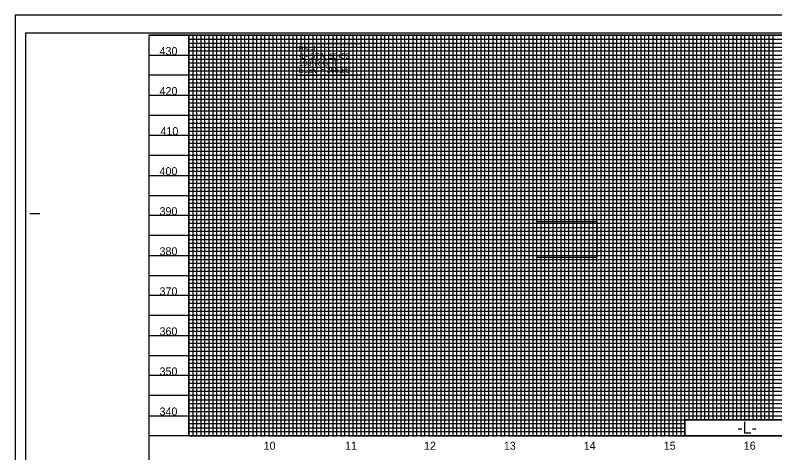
# Model space of a CAD drawing. Extents: x 1629887 to 1632095, y 1174261 to 1175361.
# Drawn here: x 1629887 to 1630837, y 1174814 to 1175361 of the extents above; entities that cross this region are included whole.
import ezdxf

# ---------------------------------------------------------------- set-up
doc = ezdxf.new("R2010")
doc.units = 0
for name, color, linetype in [('Exist Vertical Profile Horizontal Axis Label Major', 7, 'Continuous'), ('Exist Vertical Profile Vertical Axis Label', 7, 'Continuous'), ('Prop DSN Text', 7, 'Continuous'), ('Prop Grid Mask', 7, 'Continuous'), ('Sheet Data Field CELL', 7, 'Continuous'), ('Sheet Layout Profile Border Port 1', 7, 'Continuous'), ('Sheet Plot Border Inside CELL', 7, 'Continuous'), ('Sheet Plot Border Outside CELL', 7, 'Continuous'), ('Sheet Profile CELL', 7, 'Continuous'), ('Sheet Profile Grid Major CELL', 7, 'Continuous'), ('Sheet Profile Grid Middle CELL', 7, 'Continuous'), ('Sheet Profile Grid Minor CELL', 7, 'Continuous')]:
    doc.layers.add(name, color=color, linetype=linetype)

msp = doc.modelspace()

# ---------------------------------------------------------------- linework, layer by layer
at = {"layer": 'Prop Grid Mask'}
for points in [[(1630239.31, 1175325.5), (1630319.31, 1175325.5), (1630319.31, 1175285.5), (1630239.31, 1175285.5)], [(1630539.31, 1175103.2), (1630614.31, 1175103.2), (1630614.31, 1175058.2), (1630539.31, 1175058.2)]]:
    msp.add_lwpolyline(points, close=True, dxfattribs=at)
at = {"layer": 'Sheet Data Field CELL'}
msp.add_lwpolyline([(1630724.31, 1174835.79), (1630884.31, 1174835.79), (1630884.31, 1174855.79), (1630724.31, 1174855.79)], close=True, dxfattribs=at)
at = {"layer": 'Sheet Layout Profile Border Port 1'}
msp.add_lwpolyline([(1630104.31, 1175335.79), (1631154.21, 1175335.79), (1631154.21, 1175309.53), (1631354.26, 1175309.53), (1631354.26, 1175174.74), (1631504.31, 1175174.74), (1631504.31, 1174860.79), (1631304.31, 1174860.79), (1631304.31, 1174835.79), (1630884.31, 1174835.79), (1630884.31, 1174855.79), (1630724.31, 1174855.79), (1630724.31, 1174835.79), (1630104.31, 1174835.79)], close=True, dxfattribs=at)
at = {"layer": 'Sheet Plot Border Inside CELL'}
msp.add_lwpolyline([(1629900.31, 1174283.24), (1631566.81, 1174283.24), (1631566.81, 1175338.34), (1629900.31, 1175338.34)], close=True, dxfattribs=at)
at = {"layer": 'Sheet Plot Border Outside CELL'}
msp.add_lwpolyline([(1629887.31, 1174260.79), (1631571.31, 1174260.79), (1631571.31, 1175360.79), (1629887.31, 1175360.79)], close=True, dxfattribs=at)
at = {"layer": 'Sheet Profile CELL'}
for p, q in [((1629905.81, 1175113.29), (1629918.31, 1175113.29)), ((1631554.31, 1174835.79), (1630054.31, 1174835.79))]:
    msp.add_line(p, q, dxfattribs=at)
msp.add_lwpolyline([(1631554.31, 1175335.79), (1630054.31, 1175335.79), (1630054.31, 1174285.79), (1631554.31, 1174285.79)], close=True, dxfattribs=at)
at = {"layer": 'Sheet Profile Grid Major CELL'}
for p, q in [((1630104.31, 1175335.79), (1630104.31, 1174835.79)), ((1630154.31, 1174835.79), (1630154.31, 1175335.79)), ((1630154.31, 1175335.79), (1630204.31, 1175335.79)), ((1630204.31, 1175335.79), (1630204.31, 1174835.79)), ((1630254.31, 1174835.79), (1630254.31, 1175335.79)), ((1630254.31, 1175335.79), (1630304.31, 1175335.79)), ((1630304.31, 1175335.79), (1630304.31, 1174835.79)), ((1630354.31, 1174835.79), (1630354.31, 1175335.79)), ((1630354.31, 1175335.79), (1630404.31, 1175335.79)), ((1630404.31, 1175335.79), (1630404.31, 1174835.79)), ((1630454.31, 1174835.79), (1630454.31, 1175335.79)), ((1630454.31, 1175335.79), (1630504.31, 1175335.79)), ((1630504.31, 1175335.79), (1630504.31, 1174835.79)), ((1630554.31, 1174835.79), (1630554.31, 1175335.79)), ((1630554.31, 1175335.79), (1630604.31, 1175335.79)), ((1630604.31, 1175335.79), (1630604.31, 1174835.79)), ((1630654.31, 1174835.79), (1630654.31, 1175335.79)), ((1630654.31, 1175335.79), (1630704.31, 1175335.79)), ((1630704.31, 1175335.79), (1630704.31, 1174835.79)), ((1630754.31, 1174855.79), (1630754.31, 1175335.79)), ((1630754.31, 1175335.79), (1630804.31, 1175335.79)), ((1630804.31, 1175335.79), (1630804.31, 1174855.79)), ((1630104.31, 1174835.79), (1630154.31, 1174835.79)), ((1630204.31, 1174835.79), (1630254.31, 1174835.79)), ((1630304.31, 1174835.79), (1630354.31, 1174835.79)), ((1630404.31, 1174835.79), (1630454.31, 1174835.79)), ((1630504.31, 1174835.79), (1630554.31, 1174835.79)), ((1630604.31, 1174835.79), (1630654.31, 1174835.79)), ((1630704.31, 1174835.79), (1630734.31, 1174835.79))]:
    msp.add_line(p, q, dxfattribs=at)
for points in [[(1630054.31, 1175310.79), (1631154.21, 1175310.79)], [(1630054.31, 1175260.79), (1631354.26, 1175260.79)], [(1631354.26, 1175210.79), (1630054.31, 1175210.79), (1630054.31, 1175160.79), (1631554.31, 1175160.79)], [(1631554.31, 1175110.79), (1630054.31, 1175110.79), (1630054.31, 1175060.79), (1631554.31, 1175060.79)], [(1631554.31, 1175010.79), (1630054.31, 1175010.79), (1630054.31, 1174960.79), (1631554.31, 1174960.79)], [(1631554.31, 1174910.79), (1630054.31, 1174910.79), (1630054.31, 1174910.79), (1630054.31, 1174860.79), (1631554.31, 1174860.79)]]:
    msp.add_lwpolyline(points, dxfattribs=at)
at = {"layer": 'Sheet Profile Grid Middle CELL'}
msp.add_line((1630054.31, 1175335.79), (1631154.21, 1175335.79), dxfattribs=at)
for points in [[(1630129.31, 1175335.79), (1630129.31, 1174835.79), (1630179.31, 1174835.79), (1630179.31, 1175335.79), (1630229.31, 1175335.79), (1630229.31, 1174835.79), (1630279.31, 1174835.79), (1630279.31, 1175335.79), (1630329.31, 1175335.79), (1630329.31, 1174835.79), (1630379.31, 1174835.79), (1630379.31, 1175335.79), (1630429.31, 1175335.79), (1630429.31, 1174835.79), (1630479.31, 1174835.79), (1630479.31, 1175335.79), (1630529.31, 1175335.79), (1630529.31, 1174835.79), (1630579.31, 1174835.79), (1630579.31, 1175335.79), (1630629.31, 1175335.79), (1630629.31, 1174835.79), (1630679.31, 1174835.79), (1630679.31, 1174835.79), (1630679.31, 1175335.79), (1630729.31, 1175335.79), (1630729.31, 1174855.79)], [(1630779.31, 1174855.79), (1630779.31, 1175335.79), (1630829.31, 1175335.79), (1630829.31, 1174855.79)], [(1631354.26, 1175285.79), (1630054.31, 1175285.79), (1630054.31, 1175235.79), (1631354.26, 1175235.79)], [(1631354.26, 1175185.79), (1630054.31, 1175185.79), (1630054.31, 1175135.79), (1631554.31, 1175135.79)], [(1631554.31, 1175085.79), (1630054.31, 1175085.79), (1630054.31, 1175035.79), (1631554.31, 1175035.79)], [(1631554.31, 1174985.79), (1630054.31, 1174985.79), (1630054.31, 1174935.79), (1631554.31, 1174935.79)], [(1631554.31, 1174885.79), (1630054.31, 1174885.79)]]:
    msp.add_lwpolyline(points, dxfattribs=at)
at = {"layer": 'Sheet Profile Grid Minor CELL'}
for p, q in [((1630104.31, 1175330.79), (1631154.21, 1175330.79)), ((1630634.31, 1175335.79), (1630634.31, 1174835.79)), ((1630639.31, 1174835.79), (1630639.31, 1175335.79)), ((1630639.31, 1175335.79), (1630644.31, 1175335.79)), ((1630644.31, 1175335.79), (1630644.31, 1174835.79)), ((1630649.31, 1174835.79), (1630649.31, 1175335.79)), ((1630649.31, 1175335.79), (1630659.31, 1175335.79)), ((1630659.31, 1175335.79), (1630659.31, 1174835.79)), ((1630664.31, 1174835.79), (1630664.31, 1175335.79)), ((1630664.31, 1175335.79), (1630669.31, 1175335.79)), ((1630669.31, 1175335.79), (1630669.31, 1174835.79)), ((1630674.31, 1174835.79), (1630674.31, 1175335.79)), ((1630674.31, 1175335.79), (1630684.31, 1175335.79)), ((1630684.31, 1175335.79), (1630684.31, 1174835.79)), ((1630689.31, 1174835.79), (1630689.31, 1175335.79)), ((1630689.31, 1175335.79), (1630694.31, 1175335.79)), ((1630694.31, 1175335.79), (1630694.31, 1174835.79)), ((1630699.31, 1174835.79), (1630699.31, 1175335.79)), ((1630699.31, 1175335.79), (1630709.31, 1175335.79)), ((1630709.31, 1175335.79), (1630709.31, 1174835.79)), ((1630714.31, 1174835.79), (1630714.31, 1175335.79)), ((1630714.31, 1175335.79), (1630719.31, 1175335.79)), ((1630719.31, 1175335.79), (1630719.31, 1174835.79)), ((1630724.31, 1174835.79), (1630724.31, 1175335.79)), ((1630724.31, 1175335.79), (1630734.31, 1175335.79)), ((1630734.31, 1175335.79), (1630734.31, 1174855.79)), ((1630739.31, 1174855.79), (1630739.31, 1175335.79)), ((1630739.31, 1175335.79), (1630744.31, 1175335.79)), ((1630744.31, 1175335.79), (1630744.31, 1174855.79)), ((1630749.31, 1174855.79), (1630749.31, 1175335.79)), ((1630749.31, 1175335.79), (1630759.31, 1175335.79)), ((1630759.31, 1175335.79), (1630759.31, 1174855.79)), ((1630104.31, 1175325.79), (1630104.31, 1175325.79)), ((1631154.21, 1175325.73), (1630104.31, 1175325.44)), ((1630104.31, 1175320.79), (1631154.21, 1175320.79)), ((1631354.31, 1175200.79), (1630104.31, 1175200.79)), ((1631354.31, 1175195.79), (1630104.31, 1175195.79)), ((1631354.31, 1175190.79), (1630104.31, 1175190.79)), ((1630104.31, 1175180.79), (1631354.31, 1175180.79)), ((1631354.31, 1175175.79), (1630104.31, 1175175.79)), ((1630104.31, 1175170.79), (1631504.31, 1175170.79)), ((1631504.31, 1175150.79), (1630104.31, 1175150.79)), ((1630104.31, 1175145.79), (1631504.31, 1175145.79)), ((1631504.31, 1175125.79), (1630104.31, 1175125.79)), ((1630104.31, 1175120.79), (1631504.31, 1175120.79)), ((1631504.31, 1175100.79), (1630104.31, 1175100.79)), ((1630104.31, 1175095.79), (1631504.31, 1175095.79)), ((1631504.31, 1175090.79), (1630104.31, 1175090.79)), ((1630104.31, 1175080.79), (1631504.31, 1175080.79)), ((1631504.31, 1175075.79), (1630104.31, 1175075.79)), ((1630104.31, 1175070.79), (1631504.31, 1175070.79)), ((1631504.31, 1175065.79), (1630104.31, 1175065.79)), ((1630104.31, 1175055.79), (1631504.31, 1175055.79)), ((1631504.31, 1175050.79), (1630104.31, 1175050.79)), ((1630104.31, 1175045.79), (1631504.31, 1175045.79)), ((1631504.31, 1175040.79), (1630104.31, 1175040.79)), ((1630104.31, 1175030.79), (1631504.31, 1175030.79)), ((1631504.31, 1175025.79), (1630104.31, 1175025.79)), ((1630104.31, 1175020.79), (1631504.31, 1175020.79)), ((1631504.31, 1175015.79), (1630104.31, 1175015.79)), ((1630104.31, 1175005.79), (1631504.31, 1175005.79)), ((1631504.31, 1175000.79), (1630104.31, 1175000.79)), ((1630104.31, 1174995.79), (1631504.31, 1174995.79)), ((1631504.31, 1174990.79), (1630104.31, 1174990.79)), ((1630104.31, 1174980.79), (1631504.31, 1174980.79)), ((1631504.31, 1174975.79), (1630104.31, 1174975.79)), ((1630104.31, 1174970.79), (1631504.31, 1174970.79)), ((1631504.31, 1174965.79), (1630104.31, 1174965.79)), ((1630104.31, 1174955.79), (1631504.31, 1174955.79)), ((1631504.31, 1174950.79), (1630104.31, 1174950.79)), ((1631504.31, 1174945.79), (1630104.31, 1174945.79)), ((1631504.31, 1174940.79), (1630104.31, 1174940.79)), ((1630104.31, 1174930.79), (1631504.31, 1174930.79)), ((1631504.31, 1174925.79), (1630104.31, 1174925.79)), ((1630104.31, 1174920.79), (1631504.31, 1174920.79)), ((1631504.31, 1174915.79), (1630104.31, 1174915.79)), ((1630104.31, 1174905.79), (1631504.31, 1174905.79)), ((1631504.31, 1174900.79), (1630104.31, 1174900.79)), ((1630104.31, 1174895.79), (1631504.31, 1174895.79)), ((1631504.31, 1174890.79), (1630104.31, 1174890.79)), ((1630104.31, 1174880.79), (1631504.31, 1174880.79)), ((1631504.31, 1174875.79), (1630104.31, 1174875.79)), ((1630104.31, 1174870.79), (1631504.31, 1174870.79)), ((1631504.31, 1174865.79), (1630104.31, 1174865.79)), ((1630104.31, 1174855.79), (1631304.31, 1174855.79)), ((1630724.31, 1174850.79), (1630104.31, 1174850.79)), ((1630104.31, 1174845.79), (1630724.31, 1174845.79)), ((1630634.31, 1174835.79), (1630639.31, 1174835.79)), ((1630644.31, 1174835.79), (1630649.31, 1174835.79)), ((1630659.31, 1174835.79), (1630664.31, 1174835.79)), ((1630669.31, 1174835.79), (1630674.31, 1174835.79)), ((1630684.31, 1174835.79), (1630689.31, 1174835.79)), ((1630694.31, 1174835.79), (1630699.31, 1174835.79)), ((1630709.31, 1174835.79), (1630714.31, 1174835.79)), ((1630719.31, 1174835.79), (1630724.31, 1174835.79)), ((1630734.31, 1174835.79), (1630739.31, 1174835.79)), ((1630744.31, 1174835.79), (1630749.31, 1174835.79))]:
    msp.add_line(p, q, dxfattribs=at)
for points in [[(1630109.31, 1175335.79), (1630109.31, 1174835.79), (1630114.31, 1174835.79), (1630114.31, 1175335.79), (1630119.31, 1175335.79), (1630119.31, 1174835.79), (1630124.31, 1174835.79), (1630124.31, 1175335.79), (1630134.31, 1175335.79), (1630134.31, 1174835.79), (1630139.31, 1174835.79), (1630139.31, 1175335.79), (1630144.31, 1175335.79), (1630144.31, 1174835.79), (1630149.31, 1174835.79), (1630159.31, 1174835.79), (1630164.31, 1174835.79), (1630164.31, 1175335.79), (1630169.31, 1175335.79), (1630169.31, 1174835.79), (1630174.31, 1174835.79), (1630174.31, 1175335.79), (1630184.31, 1175335.79), (1630184.31, 1174835.79), (1630189.31, 1174835.79), (1630189.31, 1175335.79), (1630194.31, 1175335.79), (1630194.31, 1174835.79), (1630199.31, 1174835.79), (1630199.31, 1175335.79), (1630209.31, 1175335.79), (1630209.31, 1174835.79), (1630214.31, 1174835.79), (1630214.31, 1175335.79), (1630219.31, 1175335.79), (1630219.31, 1174835.79), (1630224.31, 1174835.79), (1630224.31, 1175335.79), (1630234.31, 1175335.79), (1630234.31, 1174835.79), (1630239.31, 1174835.79), (1630239.31, 1175335.79), (1630244.31, 1175335.79), (1630244.31, 1174835.79), (1630249.31, 1174835.79), (1630249.31, 1175335.79), (1630259.31, 1175335.79), (1630259.31, 1174835.79), (1630264.31, 1174835.79), (1630264.31, 1175335.79), (1630269.31, 1175335.79), (1630269.31, 1174835.79), (1630274.31, 1174835.79), (1630274.31, 1175335.79), (1630284.31, 1175335.79), (1630284.31, 1174835.79), (1630289.31, 1174835.79), (1630289.31, 1175335.79), (1630294.31, 1175335.79), (1630294.31, 1174835.79), (1630299.31, 1174835.79), (1630299.31, 1175335.79), (1630309.31, 1175335.79), (1630309.31, 1174835.79), (1630314.31, 1174835.79), (1630314.31, 1175335.79), (1630319.31, 1175335.79), (1630319.31, 1174835.79)], [(1630149.31, 1174835.79), (1630149.31, 1175335.79), (1630159.31, 1175335.79), (1630159.31, 1174835.79)], [(1630319.31, 1174835.79), (1630324.31, 1174835.79), (1630324.31, 1175335.79), (1630334.31, 1175335.79), (1630334.31, 1174835.79), (1630339.31, 1174835.79), (1630339.31, 1175335.79), (1630344.31, 1175335.79), (1630344.31, 1174835.79), (1630349.31, 1174835.79), (1630349.31, 1175335.79), (1630359.31, 1175335.79), (1630359.31, 1174835.79), (1630364.31, 1174835.79), (1630364.31, 1175335.79), (1630369.31, 1175335.79), (1630369.31, 1174835.79), (1630374.31, 1174835.79), (1630374.31, 1175335.79), (1630384.31, 1175335.79), (1630384.31, 1174835.79), (1630389.31, 1174835.79), (1630389.31, 1175335.79), (1630394.31, 1175335.79), (1630394.31, 1174835.79), (1630399.31, 1174835.79), (1630399.31, 1175335.79), (1630409.31, 1175335.79), (1630409.31, 1174835.79), (1630414.31, 1174835.79), (1630414.31, 1175335.79), (1630419.31, 1175335.79), (1630419.31, 1174835.79), (1630424.31, 1174835.79), (1630424.31, 1175335.79), (1630434.31, 1175335.79), (1630434.31, 1174835.79), (1630439.31, 1174835.79), (1630439.31, 1175335.79), (1630444.31, 1175335.79), (1630444.31, 1174835.79), (1630449.31, 1174835.79), (1630449.31, 1175335.79), (1630459.31, 1175335.79), (1630459.31, 1174835.79), (1630464.31, 1174835.79), (1630464.31, 1175335.79), (1630469.31, 1175335.79), (1630469.31, 1174835.79), (1630474.31, 1174835.79), (1630474.31, 1175335.79), (1630484.31, 1175335.79), (1630484.31, 1174835.79), (1630489.31, 1174835.79), (1630489.31, 1175335.79), (1630494.31, 1175335.79), (1630494.31, 1174835.79), (1630499.31, 1174835.79), (1630499.31, 1175335.79), (1630509.31, 1175335.79), (1630509.31, 1174835.79), (1630514.31, 1174835.79), (1630514.31, 1175335.79), (1630519.31, 1175335.79), (1630519.31, 1174835.79), (1630524.31, 1174835.79), (1630524.31, 1175335.79), (1630534.31, 1175335.79), (1630534.31, 1174835.79), (1630539.31, 1174835.79), (1630539.31, 1175335.79), (1630544.31, 1175335.79), (1630544.31, 1174835.79), (1630549.31, 1174835.79), (1630549.31, 1175335.79), (1630559.31, 1175335.79), (1630559.31, 1174835.79), (1630564.31, 1174835.79), (1630564.31, 1175335.79), (1630569.31, 1175335.79), (1630569.31, 1174835.79), (1630574.31, 1174835.79), (1630574.31, 1175335.79), (1630584.31, 1175335.79), (1630584.31, 1174835.79), (1630589.31, 1174835.79), (1630589.31, 1175335.79), (1630594.31, 1175335.79), (1630594.31, 1174835.79), (1630599.31, 1174835.79), (1630599.31, 1175335.79), (1630609.31, 1175335.79), (1630609.31, 1174835.79), (1630614.31, 1174835.79), (1630614.31, 1175335.79), (1630619.31, 1175335.79), (1630619.31, 1174835.79), (1630624.31, 1174835.79), (1630624.31, 1175335.79), (1630634.31, 1175335.79)], [(1630764.31, 1174855.79), (1630764.31, 1175335.79), (1630769.31, 1175335.79), (1630769.31, 1174855.79)], [(1630774.31, 1174855.79), (1630774.31, 1175335.79), (1630784.31, 1175335.79), (1630784.31, 1174855.79)], [(1630789.31, 1174855.79), (1630789.31, 1175335.79), (1630794.31, 1175335.79), (1630794.31, 1174855.79)], [(1630799.31, 1174855.79), (1630799.31, 1175335.79), (1630809.31, 1175335.79), (1630809.31, 1174855.79)], [(1630814.31, 1174855.79), (1630814.31, 1175335.79), (1630819.31, 1175335.79), (1630819.31, 1174855.79)], [(1630824.31, 1174855.79), (1630824.31, 1175335.79), (1630834.31, 1175335.79), (1630834.31, 1174855.79)], [(1631154.21, 1175315.79), (1630104.31, 1175315.79), (1630104.31, 1175305.79), (1631354.26, 1175305.79)], [(1631354.26, 1175300.79), (1630104.31, 1175300.79), (1630104.31, 1175295.79), (1631354.26, 1175295.79)], [(1631354.26, 1175290.79), (1630104.31, 1175290.79), (1630104.31, 1175280.79), (1631354.26, 1175280.79)], [(1631354.26, 1175275.79), (1630104.31, 1175275.79), (1630104.31, 1175270.79), (1631354.26, 1175270.79)], [(1631354.26, 1175265.79), (1630104.31, 1175265.79), (1630104.31, 1175255.79), (1631354.26, 1175255.79)], [(1631354.26, 1175250.79), (1630104.31, 1175250.79), (1630104.31, 1175245.79), (1631354.26, 1175245.79)], [(1631354.26, 1175240.79), (1630104.31, 1175240.79), (1630104.31, 1175230.79), (1631354.26, 1175230.79)], [(1631354.26, 1175225.69), (1630104.41, 1175225.69), (1630104.41, 1175220.79), (1631354.26, 1175220.79)], [(1631354.26, 1175215.79), (1630104.31, 1175215.79), (1630104.31, 1175205.79), (1631354.26, 1175205.79)], [(1631504.31, 1175165.79), (1630104.31, 1175165.79), (1630104.31, 1175155.79), (1631504.31, 1175155.79)], [(1631504.31, 1175140.79), (1630104.31, 1175140.79), (1630104.31, 1175130.79), (1631504.31, 1175130.79)], [(1631504.31, 1175115.79), (1630104.31, 1175115.79), (1630104.31, 1175105.79), (1631504.31, 1175105.79)], [(1630724.31, 1174840.79), (1630104.31, 1174840.79)]]:
    msp.add_lwpolyline(points, dxfattribs=at)

# ---------------------------------------------------------------- texts
at = {"layer": 'Exist Vertical Profile Horizontal Axis Label Major'}
for s, p in [('10', (1630197.9, 1174818.29)), ('11', (1630299.74, 1174818.29)), ('12', (1630398.29, 1174818.29)), ('13', (1630498.12, 1174818.29)), ('14', (1630597.96, 1174818.29)), ('15', (1630698.05, 1174818.29)), ('16', (1630798, 1174818.29))]:
    msp.add_text(s, height=10, dxfattribs=at).set_placement(p)
at = {"layer": 'Exist Vertical Profile Vertical Axis Label'}
for s, p in [('430', (1630067.75, 1175311.04)), ('420', (1630067.75, 1175261.04)), ('410', (1630068.94, 1175211.04)), ('400', (1630067.75, 1175161.04)), ('390', (1630067.75, 1175111.04)), ('380', (1630067.75, 1175061.04)), ('370', (1630067.75, 1175011.04)), ('360', (1630067.75, 1174961.04)), ('350', (1630067.75, 1174911.04)), ('340', (1630067.75, 1174861.04))]:
    msp.add_text(s, height=10, dxfattribs=at).set_placement(p)
at = {"layer": 'Prop DSN Text'}
for s, p in [('BM-1', (1630241.84, 1175315.31)), ('-L- STA. 10+52', (1630241.84, 1175306.43)), ("193' RIGHT", (1630241.84, 1175297.56)), ("ELEV = 365.86'", (1630241.84, 1175288.68))]:
    msp.add_text(s, height=7, rotation=360, dxfattribs=at).set_placement(p)
at = {"layer": 'Sheet Data Field CELL'}
msp.add_text('-L-', height=15, rotation=360, dxfattribs=at).set_placement((1630789.88, 1174838.29))

doc.saveas('drawing.dxf')
